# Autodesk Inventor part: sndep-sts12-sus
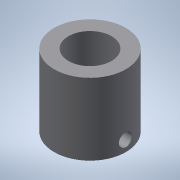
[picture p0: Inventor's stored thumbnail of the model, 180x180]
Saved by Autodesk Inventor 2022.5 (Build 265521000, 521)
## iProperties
Created: 2016-12
Part Number: sndep-sts12-sus
Material: 一般
Document SubType Name: Modeling
Designer: imaocorp
Density: 1 g/cm^3
Appearance: 既定
Author: imaocorp
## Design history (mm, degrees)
node "sndep-sts12-sus.x_t1"
node "sndep-sts12-sus"
node "Base1"
